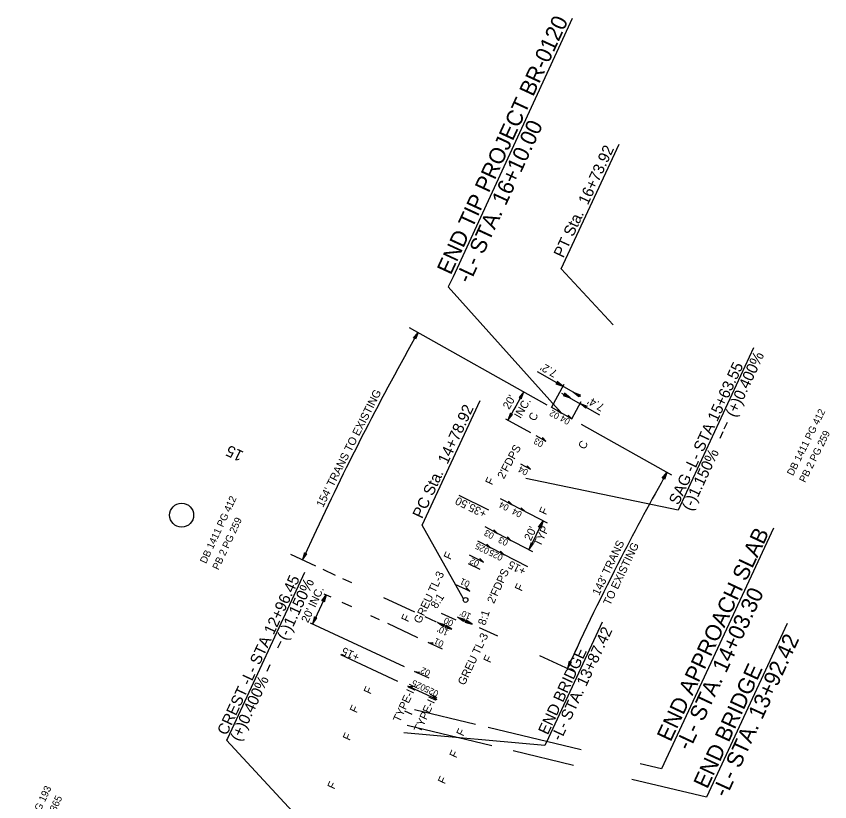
# Model space of a CAD drawing. Extents: x 2532362 to 2533150, y 715234 to 716115.
# Drawn here: x 2532642 to 2533150, y 715625 to 716115 of the extents above; entities that cross this region are included whole.
import ezdxf

# ---------------------------------------------------------------- set-up
doc = ezdxf.new("R2010")
doc.units = 0
for name, color, linetype in [('Default', 7, 'Continuous'), ('Exist Property Deed Book Text', 7, 'Continuous'), ('Old_Level_1', 7, 'Continuous'), ('Prop Dimension', 7, 'Continuous'), ('Prop Dimension Text', 7, 'Continuous'), ('Prop DSN Text', 7, 'Continuous'), ('Prop Horizontal Alignment Station Label', 7, 'Continuous'), ('Prop Horizontal Alignment Tick Label', 7, 'Continuous'), ('Prop Horizontal Alignment Tick Large', 7, 'Continuous'), ('Prop Horizontal Alignment Tick Small', 7, 'Continuous'), ('Prop Plan Preparation Crest Label', 7, 'Continuous'), ('Prop Plan Preparation Sag Label', 7, 'Continuous'), ('Scratch_Level_0', 7, 'Continuous')]:
    doc.layers.add(name, color=color, linetype=linetype)

msp = doc.modelspace()

# ---------------------------------------------------------------- linework, layer by layer
at = {"layer": 'Old_Level_1'}
for points in [[(2533115.15, 715795.87), (2533045.24, 715645.6), (2533045.24, 715645.6)], [(2533123.7, 715736.37), (2533073.25, 715627.94), (2533073.25, 715627.94)], [(2532928.93, 715673.43), (2532890.94, 715682.52)], [(2532939.2, 715660.02), (2532886.34, 715672.66)], [(2532994.92, 715657.64), (2532936.88, 715671.53)], [(2532990.2, 715647.81), (2532952.52, 715656.83)], [(2533045.24, 715645.6), (2533031.8, 715648.81)], [(2533073.25, 715627.94), (2533026.68, 715639.08)]]:
    msp.add_lwpolyline(points, dxfattribs=at)
at = {"layer": 'Prop Dimension'}
for p, q in [((2532973.86, 715872.64), (2532887.92, 715921)), ((2532994.77, 715878), (2532967.83, 715893.47)), ((2532976.41, 715871.2), (2532984.32, 715885.73)), ((2532982.81, 715880.22), (2533006.51, 715866.68)), ((2532976.46, 715871.3), (2532989.08, 715864.07)), ((2532989.08, 715864.07), (2532995.09, 715874.99)), ((2532947.8, 715864.1), (2532963.46, 715855.48)), ((2533051.54, 715828.92), (2532995.19, 715860.63)), ((2532966.7, 715853.7), (2532972.98, 715850.25)), ((2532957.13, 715835.98), (2532963.45, 715832.6)), ((2532937.27, 715807.1), (2532918.82, 715816.27)), ((2532951.86, 715810.43), (2532944.63, 715814.14)), ((2532974.08, 715799.04), (2532951.87, 715810.44)), ((2532971.12, 715800.34), (2532962.51, 715782.67)), ((2532829.59, 715794.46), (2532821.07, 715776.13)), ((2532942.84, 715792.6), (2532934.98, 715796.61)), ((2532964.75, 715781.17), (2532942.75, 715792.64)), ((2532961.65, 715771.68), (2532930.43, 715787.74)), ((2532813.61, 715779.6), (2532829.1, 715772.39)), ((2532934.03, 715774.68), (2532925.35, 715779.02)), ((2532833.64, 715770.28), (2532841.44, 715766.65)), ((2532845.97, 715764.54), (2532851.55, 715761.95)), ((2532835.73, 715754.21), (2532827.29, 715736.07)), ((2532838.85, 715752.75), (2532834.52, 715754.76)), ((2532851.79, 715746.73), (2532845.71, 715749.56)), ((2532871.59, 715752.62), (2532890.89, 715743.65)), ((2532869.04, 715738.7), (2532863.78, 715741.15)), ((2532897.3, 715740.66), (2532904.45, 715737.34)), ((2532917.81, 715740.28), (2532926.87, 715736.07)), ((2532884.72, 715709.35), (2532826.08, 715736.63)), ((2532893.04, 715727.54), (2532874.23, 715736.29)), ((2532914.31, 715732.75), (2532905.24, 715736.97)), ((2532931.39, 715733.96), (2532942.83, 715728.64)), ((2532880.5, 715700.29), (2532844.88, 715716.86)), ((2532969.04, 715716.45), (2532990.65, 715706.39))]:
    msp.add_line(p, q, dxfattribs=at)
for points in [[(2532890.25, 715914.53), (2532893.16, 715918.05), (2532891.6, 715913.73), (2532891.19, 715914.62)], [(2532979.23, 715886.03), (2532983.52, 715884.46), (2532980, 715887.41), (2532980.1, 715886.43)], [(2532957.61, 715876.62), (2532959.13, 715880.93), (2532956.23, 715877.36), (2532957.2, 715877.48)], [(2532993.57, 715877.79), (2532990.06, 715880.7), (2532994.38, 715879.14), (2532993.48, 715878.74)], [(2532983.77, 715878.76), (2532988.06, 715877.22), (2532984.52, 715880.15), (2532984.63, 715879.17)], [(2532997.86, 715870.75), (2532994.33, 715873.64), (2532998.66, 715872.11), (2532997.77, 715871.7)], [(2532950.83, 715867.57), (2532949.32, 715863.26), (2532952.22, 715866.83), (2532951.24, 715866.71)], [(2532982.68, 715867.73), (2532980.56, 715870.08), (2532980.67, 715868.87)], [(2532989.08, 715864.07), (2532986.95, 715866.41), (2532987.06, 715865.21)], [(2532972.98, 715850.25), (2532970.81, 715852.55), (2532970.94, 715851.35)], [(2532963.45, 715832.6), (2532961.26, 715834.88), (2532961.4, 715833.67)], [(2533045.66, 715827.08), (2533048.57, 715830.59), (2533047.01, 715826.27), (2533046.6, 715827.17)], [(2532951.85, 715810.47), (2532949.61, 715812.7), (2532949.78, 715811.5)], [(2532959.8, 715806.39), (2532957.56, 715808.63), (2532957.73, 715807.42)], [(2532968.39, 715796.6), (2532971.2, 715800.52), (2532969.87, 715795.85), (2532969.38, 715796.77)], [(2532942.82, 715792.63), (2532940.58, 715794.86), (2532940.75, 715793.66)], [(2532951.19, 715788.24), (2532948.99, 715790.51), (2532949.14, 715789.31)], [(2532938.4, 715783.64), (2532936.19, 715785.9), (2532936.35, 715784.69)], [(2532963.7, 715786.77), (2532962.38, 715782.4), (2532965.12, 715786.09), (2532964.15, 715785.93)], [(2532822.27, 715780.54), (2532821.07, 715776.13), (2532823.7, 715779.89), (2532822.73, 715779.71)], [(2532946.86, 715779.28), (2532944.65, 715781.55), (2532944.81, 715780.34)], [(2532933.95, 715774.72), (2532931.71, 715776.96), (2532931.88, 715775.76)], [(2532925.41, 715756.6), (2532923.11, 715758.77), (2532923.32, 715757.57)], [(2532833.13, 715750.46), (2532835.73, 715754.21), (2532834.55, 715749.77), (2532834.06, 715750.63)], [(2532828.49, 715740.48), (2532827.29, 715736.07), (2532829.93, 715739.83), (2532828.96, 715739.65)], [(2532921.56, 715737.68), (2532917.81, 715740.28), (2532922.25, 715739.1), (2532921.39, 715738.61)], [(2532922.45, 715737.18), (2532926.88, 715736.06), (2532923.07, 715738.63), (2532923.27, 715737.67)], [(2532908.99, 715734.37), (2532905.24, 715736.97), (2532909.68, 715735.78), (2532908.82, 715735.3)], [(2532909.88, 715733.87), (2532914.31, 715732.75), (2532910.5, 715735.32), (2532910.7, 715734.36)], [(2532899.46, 715724.55), (2532902.61, 715724.22), (2532901.57, 715723.59)], [(2532987.57, 715712.79), (2532986.37, 715708.38), (2532989.01, 715712.15), (2532988.04, 715711.96)], [(2532891.03, 715706.42), (2532894.17, 715706.09), (2532893.13, 715705.46)], [(2532886.81, 715697.35), (2532889.95, 715697.02), (2532888.91, 715696.39)], [(2532904.94, 715688.91), (2532902.64, 715691.09), (2532902.84, 715689.89)]]:
    msp.add_lwpolyline(points, close=True, dxfattribs=at)
for centre, radius, start, end in [((2534407.55, 715060.95), 1740.11, 150.49155, 155.0687), ((2534464.19, 715033.98), 1727, 150.63202, 151.30229), ((2534460, 715035.21), 1620.11, 150.59949, 152.72887), ((2534460, 715035.21), 1620.11, 152.72887, 155.44862)]:
    msp.add_arc(centre, radius, start, end, dxfattribs=at)
at = {"layer": 'Prop Dimension Text'}
for p, q in [((2532925.41, 715756.6), (2532916.35, 715760.81)), ((2532916.97, 715738.47), (2532907.9, 715742.68)), ((2532908.53, 715720.33), (2532899.46, 715724.55)), ((2532900.09, 715702.2), (2532891.03, 715706.42)), ((2532895.87, 715693.13), (2532886.81, 715697.35)), ((2532904.94, 715688.91), (2532895.87, 715693.13))]:
    msp.add_line(p, q, dxfattribs=at)
msp.add_circle((2532745.59, 715803.99), 7.5, dxfattribs=at)
at = {"layer": 'Prop DSN Text'}
msp.add_line((2532989.41, 716114), (2532914.99, 715952.79), dxfattribs=at)
msp.add_lwpolyline([(2532914.99, 715952.79), (2532912.04, 715946.4), (2532982.66, 715867.69)], dxfattribs=at)
at = {"layer": 'Prop Horizontal Alignment Station Label'}
for p, q in [((2532982.5, 715957.63), (2533018.77, 716035.58)), ((2533015.04, 715922.79), (2532982.5, 715957.63)), ((2532895.72, 715797.81), (2532931.86, 715875.49)), ((2532921.52, 715751.8), (2532895.72, 715797.81))]:
    msp.add_line(p, q, dxfattribs=at)
msp.add_circle((2532922.84, 715751.08), 1.5, dxfattribs=at)
at = {"layer": 'Prop Horizontal Alignment Tick Large'}
msp.add_line((2532931.85, 715770.14), (2532924.64, 715773.61), dxfattribs=at)
at = {"layer": 'Prop Horizontal Alignment Tick Small'}
msp.add_line((2532889.55, 715679.53), (2532885.01, 715681.64), dxfattribs=at)
at = {"layer": 'Prop Plan Preparation Crest Label'}
for p, q in [((2532822.32, 715768.11), (2532774.18, 715664.62)), ((2532807.44, 715725.07), (2532805.5, 715720.91)), ((2532798.88, 715706.68), (2532800.82, 715710.84))]:
    msp.add_line(p, q, dxfattribs=at)
msp.add_lwpolyline([(2532774.18, 715664.62), (2532773.69, 715663.57), (2532845.86, 715585.65)], dxfattribs=at)
at = {"layer": 'Prop Plan Preparation Sag Label'}
for p, q in [((2533102.68, 715908.43), (2533056.65, 715809.49)), ((2533084.33, 715857.9), (2533086.27, 715862.06)), ((2533083.41, 715855.93), (2533081.48, 715851.76))]:
    msp.add_line(p, q, dxfattribs=at)
msp.add_lwpolyline([(2533056.65, 715809.49), (2533055.57, 715807.17), (2532960.42, 715826.91)], dxfattribs=at)
at = {"layer": 'Scratch_Level_0'}
msp.add_line((2533008.21, 715737.29), (2532974.54, 715664.94), dxfattribs=at)
msp.add_lwpolyline([(2532974.54, 715664.94), (2532972.37, 715660.26), (2532884.24, 715668.13)], dxfattribs=at)

# ---------------------------------------------------------------- texts
at = {"layer": 'Default'}
for s, p in [('C', (2532966.36, 715862.32)), ('C', (2532997.43, 715844.67)), ('F', (2532939.39, 715822.43)), ('F', (2532972.99, 715803.79)), ('F', (2532913.41, 715775.81)), ('F', (2532957.81, 715756.12)), ('F', (2532886.9, 715736.97)), ('F', (2532938.18, 715711.4)), ('F', (2532863.46, 715691.9)), ('F', (2532854.77, 715680.16)), ('F', (2532850.42, 715662.92)), ('F', (2532921.31, 715665.65)), ('F', (2532917.01, 715652.06)), ('F', (2532840.81, 715632.57)), ('F', (2532909.78, 715635.81))]:
    msp.add_text(s, height=5, rotation=65.05, dxfattribs=at).set_placement(p)
at = {"layer": 'Exist Property Deed Book Text'}
for s, rotation, p in [('DB 1411 PG 412', 63.3607, (2533127.2, 715828.18)), ('PB 2 PG 259', 63.3607, (2533134.84, 715823.99)), ('DB 1411 PG 412', 65.05, (2532760.81, 715773.4)), ('PB 2 PG 259', 65.05, (2532768.58, 715769.44)), ('DB N10 PG 193', 65.05, (2532646.22, 715594.66)), ('PB R29 PG 365', 65.05, (2532653.15, 715588.9))]:
    msp.add_text(s, height=4.5, rotation=rotation, dxfattribs=at).set_placement(p)
at = {"layer": 'Old_Level_1'}
for s, rotation, p in [('END APPROACH SLAB', 64.7988, (2533050.84, 715662.04)), ('-L- STA. 14+03.30', 64.7988, (2533062.61, 715656.51)), ('-L- STA. 13+92.42', 65.3012, (2533085.56, 715627.26)), ('END BRIDGE', 65.3012, (2533073.75, 715632.69))]:
    msp.add_text(s, height=10, rotation=rotation, dxfattribs=at).set_placement(p)
at = {"layer": 'Prop Dimension Text'}
for s, height, rotation, p in [("7.2'", 5, 150.2871, (2532980.55, 715893.93)), ("154' TRANS TO EXISTING", 5, 63.2168, (2532833.82, 715808.43)), ("20'", 5, 59.9456, (2532950.02, 715869.58)), ('INC.', 5, 59.9456, (2532957.13, 715863.89)), ("7.4'", 5, 150.2625, (2533009.99, 715872.76)), ('02', 4, 150.0254, (2532981.83, 715866.97)), ('04', 4, 150.0254, (2532988.53, 715863.58)), ('03', 4, 151.0053, (2532972, 715849.54)), ('04', 4, 151.7071, (2532962.35, 715831.96)), ('+35.50', 5, 153.5417, (2532936.48, 715806.43)), ('04', 4, 152.6709, (2532950.36, 715809.93)), ('04', 4, 151.879, (2532958.49, 715805.74)), ('03', 4, 152.0166, (2532941.06, 715792.32)), ('03', 4, 153.4975, (2532949.86, 715788.09)), ('025', 4, 152.7788, (2532938.03, 715782.87)), ("143' TRANS", 5, 64.4785, (2533006.18, 715753.49)), ('TO EXISTING', 5, 64.4785, (2533013.01, 715747.27)), ('025', 4, 152.7788, (2532946.61, 715778.76)), ('02', 4, 153.4529, (2532931.88, 715775.08)), ('+15', 5, 152.7788, (2532961.1, 715770.61)), ('01', 4, 155.05, (2532925.94, 715762.38)), ("20' INC.", 5, 65.05, (2532824.49, 715736.4)), ('00', 4, 155.05, (2532915.75, 715737.94)), ('01', 4, 155.05, (2532909.67, 715725.06)), ('+15', 5, 155.0135, (2532857.18, 715717.02)), ('02', 4, 155.05, (2532901.28, 715706.82)), ('025', 4, 155.05, (2532898.45, 715697.62)), ('025', 4, 155.05, (2532906.39, 715694.02))]:
    msp.add_text(s, height=height, rotation=rotation, dxfattribs=at).set_placement(p)
at = {"layer": 'Prop DSN Text'}
for s, height, rotation, p in [('END TIP PROJECT BR-0120', 10, 65.219, (2532913.62, 715953.42)), ('-L- STA. 16+10.00', 10, 65.219, (2532925.43, 715947.97)), ("2'FDPS", 5, 61.4599, (2532946.73, 715826.17)), ("20'", 5, 64.0301, (2532963.57, 715787.53)), ('TYP', 5, 64.0301, (2532969.45, 715784.01)), ('GREU TL-3', 5, 64.6263, (2532894.67, 715735.92)), ("2'FDPS", 5, 65.05, (2532940.53, 715748.4)), ('8:1', 5, 57.9231, (2532904.82, 715745.21)), ("10'", 4, 155.0412, (2532926.71, 715742.19)), ('8:1', 5, 72.1783, (2532935.15, 715734.89)), ("10'", 4, 155.0412, (2532912.69, 715732.06)), ('GREU TL-3', 5, 64.6263, (2532922.21, 715697.43)), ('TYPE-III', 5, 65.05, (2532881.8, 715674.36)), ('TYPE-III', 5, 65.05, (2532894.78, 715668.07))]:
    msp.add_text(s, height=height, rotation=rotation, dxfattribs=at).set_placement(p)
at = {"layer": 'Prop Horizontal Alignment Station Label'}
for s, p in [('PT Sta.  16+73.92', (2532983.79, 715964.13)), ('PC Sta.  14+78.92', (2532895.7, 715801.37))]:
    msp.add_text(s, height=7, rotation=65.05, dxfattribs=at).set_placement(p)
at = {"layer": 'Prop Horizontal Alignment Tick Label'}
msp.add_text('15', height=7, rotation=154.3394, dxfattribs=at).set_placement((2532784.79, 715843.39))
at = {"layer": 'Prop Plan Preparation Crest Label'}
for s, p in [('CREST -L- STA 12+96.45', (2532773.77, 715666.12)), ('(+)0.400%          (-)1.150%', (2532781.93, 715662.32))]:
    msp.add_text(s, height=7, rotation=65.05, dxfattribs=at).set_placement(p)
at = {"layer": 'Prop Plan Preparation Sag Label'}
for s, p in [('(-)1.150%         (+)0.400%', (2533063.9, 715806.12)), ('SAG -L- STA 15+63.55', (2533055.74, 715809.92))]:
    msp.add_text(s, height=7, rotation=65.05, dxfattribs=at).set_placement(p)
at = {"layer": 'Scratch_Level_0'}
for s, p in [('-L- STA. 13+87.42', (2532982.3, 715662.64)), ('END BRIDGE', (2532974.14, 715666.44))]:
    msp.add_text(s, height=7, rotation=65.05, dxfattribs=at).set_placement(p)

doc.saveas('drawing.dxf')
